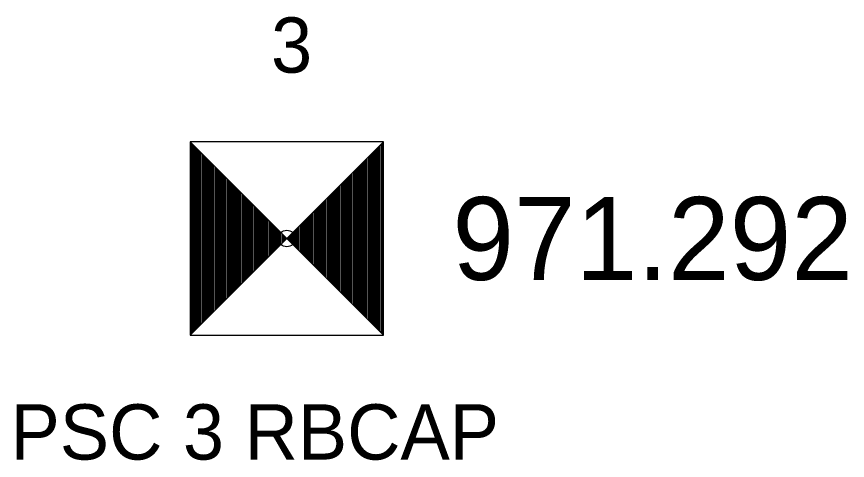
# Model space of a CAD drawing. Extents: x 1393163 to 1398407, y 1072670 to 1074651.
# Drawn here: x 1393937.48 to 1393952.52, y 1073673.99 to 1073682.02 of the extents above; entities that cross this region are included whole.
import ezdxf

# ---------------------------------------------------------------- set-up
doc = ezdxf.new("R2010")
doc.units = 0
for name, color, linetype in [('RD_HC_Survey', 7, 'Continuous'), ('RD_HC_Survey_ELEV', 7, 'Continuous'), ('RD_HC_txCode', 7, 'Continuous'), ('RD_SMD_Locator', 7, 'Continuous')]:
    doc.layers.add(name, color=color, linetype=linetype)

msp = doc.modelspace()

# ---------------------------------------------------------------- linework, layer by layer
at = {"layer": 'RD_HC_Survey'}
for p, q in [((1393940.624, 1073679.758), (1393944.124, 1073676.259)), ((1393944.124, 1073679.758), (1393940.624, 1073676.259)), ((1393940.649, 1073679.734), (1393940.649, 1073676.283)), ((1393944.1, 1073679.734), (1393944.1, 1073676.283)), ((1393940.674, 1073679.709), (1393940.674, 1073676.308)), ((1393940.699, 1073679.684), (1393940.699, 1073676.333)), ((1393940.723, 1073679.659), (1393940.723, 1073676.358)), ((1393940.748, 1073679.635), (1393940.748, 1073676.382)), ((1393940.773, 1073679.61), (1393940.773, 1073676.407)), ((1393940.798, 1073679.585), (1393940.798, 1073676.432)), ((1393943.951, 1073679.585), (1393943.951, 1073676.432)), ((1393943.976, 1073679.61), (1393943.976, 1073676.407)), ((1393944.001, 1073679.635), (1393944.001, 1073676.382)), ((1393944.025, 1073679.659), (1393944.025, 1073676.358)), ((1393944.05, 1073679.684), (1393944.05, 1073676.333)), ((1393944.075, 1073679.709), (1393944.075, 1073676.308)), ((1393940.822, 1073679.561), (1393940.822, 1073676.456)), ((1393940.847, 1073679.536), (1393940.847, 1073676.481)), ((1393940.872, 1073679.511), (1393940.872, 1073676.506)), ((1393940.897, 1073679.486), (1393940.897, 1073676.531)), ((1393940.921, 1073679.462), (1393940.921, 1073676.555)), ((1393940.946, 1073679.437), (1393940.946, 1073676.58)), ((1393943.803, 1073679.437), (1393943.803, 1073676.58)), ((1393943.827, 1073679.462), (1393943.827, 1073676.555)), ((1393943.852, 1073679.486), (1393943.852, 1073676.531)), ((1393943.877, 1073679.511), (1393943.877, 1073676.506)), ((1393943.902, 1073679.536), (1393943.902, 1073676.481)), ((1393943.926, 1073679.561), (1393943.926, 1073676.456)), ((1393940.971, 1073679.412), (1393940.971, 1073676.605)), ((1393940.996, 1073679.387), (1393940.996, 1073676.63)), ((1393941.02, 1073679.363), (1393941.02, 1073676.654)), ((1393941.045, 1073679.338), (1393941.045, 1073676.679)), ((1393941.07, 1073679.313), (1393941.07, 1073676.704)), ((1393941.095, 1073679.288), (1393941.095, 1073676.729)), ((1393943.654, 1073679.288), (1393943.654, 1073676.729)), ((1393943.679, 1073679.313), (1393943.679, 1073676.704)), ((1393943.704, 1073679.338), (1393943.704, 1073676.679)), ((1393943.728, 1073679.363), (1393943.728, 1073676.654)), ((1393943.753, 1073679.387), (1393943.753, 1073676.63)), ((1393943.778, 1073679.412), (1393943.778, 1073676.605)), ((1393941.119, 1073679.264), (1393941.119, 1073676.753)), ((1393941.144, 1073679.239), (1393941.144, 1073676.778)), ((1393941.169, 1073679.214), (1393941.169, 1073676.803)), ((1393941.194, 1073679.189), (1393941.194, 1073676.828)), ((1393941.218, 1073679.165), (1393941.218, 1073676.852)), ((1393941.243, 1073679.14), (1393941.243, 1073676.877)), ((1393943.506, 1073679.14), (1393943.506, 1073676.877)), ((1393943.53, 1073679.165), (1393943.53, 1073676.852)), ((1393943.555, 1073679.189), (1393943.555, 1073676.828)), ((1393943.58, 1073679.214), (1393943.58, 1073676.803)), ((1393943.605, 1073679.239), (1393943.605, 1073676.778)), ((1393943.629, 1073679.264), (1393943.629, 1073676.753)), ((1393941.268, 1073679.115), (1393941.268, 1073676.902)), ((1393941.293, 1073679.09), (1393941.293, 1073676.927)), ((1393941.317, 1073679.066), (1393941.317, 1073676.951)), ((1393941.342, 1073679.041), (1393941.342, 1073676.976)), ((1393941.367, 1073679.016), (1393941.367, 1073677.001)), ((1393941.392, 1073678.991), (1393941.392, 1073677.026)), ((1393943.357, 1073678.991), (1393943.357, 1073677.026)), ((1393943.382, 1073679.016), (1393943.382, 1073677.001)), ((1393943.407, 1073679.041), (1393943.407, 1073676.976)), ((1393943.431, 1073679.066), (1393943.431, 1073676.951)), ((1393943.456, 1073679.09), (1393943.456, 1073676.927)), ((1393943.481, 1073679.115), (1393943.481, 1073676.902)), ((1393941.416, 1073678.967), (1393941.416, 1073677.05)), ((1393941.441, 1073678.942), (1393941.441, 1073677.075)), ((1393941.466, 1073678.917), (1393941.466, 1073677.1)), ((1393941.491, 1073678.892), (1393941.491, 1073677.125)), ((1393941.515, 1073678.868), (1393941.515, 1073677.149)), ((1393941.54, 1073678.843), (1393941.54, 1073677.174)), ((1393943.209, 1073678.843), (1393943.209, 1073677.174)), ((1393943.233, 1073678.868), (1393943.233, 1073677.149)), ((1393943.258, 1073678.892), (1393943.258, 1073677.125)), ((1393943.283, 1073678.917), (1393943.283, 1073677.1)), ((1393943.308, 1073678.942), (1393943.308, 1073677.075)), ((1393943.332, 1073678.967), (1393943.332, 1073677.05)), ((1393941.565, 1073678.818), (1393941.565, 1073677.199)), ((1393941.59, 1073678.793), (1393941.59, 1073677.224)), ((1393941.614, 1073678.769), (1393941.614, 1073677.248)), ((1393941.639, 1073678.744), (1393941.639, 1073677.273)), ((1393941.664, 1073678.719), (1393941.664, 1073677.298)), ((1393941.689, 1073678.694), (1393941.689, 1073677.323)), ((1393943.06, 1073678.694), (1393943.06, 1073677.323)), ((1393943.085, 1073678.719), (1393943.085, 1073677.298)), ((1393943.11, 1073678.744), (1393943.11, 1073677.273)), ((1393943.134, 1073678.769), (1393943.134, 1073677.248)), ((1393943.159, 1073678.793), (1393943.159, 1073677.224)), ((1393943.184, 1073678.818), (1393943.184, 1073677.199)), ((1393941.713, 1073678.67), (1393941.713, 1073677.347)), ((1393941.738, 1073678.645), (1393941.738, 1073677.372)), ((1393941.763, 1073678.62), (1393941.763, 1073677.397)), ((1393941.788, 1073678.595), (1393941.788, 1073677.422)), ((1393941.812, 1073678.571), (1393941.812, 1073677.446)), ((1393941.837, 1073678.546), (1393941.837, 1073677.471)), ((1393941.862, 1073678.521), (1393941.862, 1073677.496)), ((1393942.887, 1073678.521), (1393942.887, 1073677.496)), ((1393942.912, 1073678.546), (1393942.912, 1073677.471)), ((1393942.936, 1073678.571), (1393942.936, 1073677.446)), ((1393942.961, 1073678.595), (1393942.961, 1073677.422)), ((1393942.986, 1073678.62), (1393942.986, 1073677.397)), ((1393943.011, 1073678.645), (1393943.011, 1073677.372)), ((1393943.035, 1073678.67), (1393943.035, 1073677.347)), ((1393941.887, 1073678.496), (1393941.887, 1073677.521)), ((1393941.911, 1073678.472), (1393941.911, 1073677.545)), ((1393941.936, 1073678.447), (1393941.936, 1073677.57)), ((1393941.961, 1073678.422), (1393941.961, 1073677.595)), ((1393941.986, 1073678.397), (1393941.986, 1073677.62)), ((1393942.01, 1073678.373), (1393942.01, 1073677.644)), ((1393942.738, 1073678.373), (1393942.738, 1073677.644)), ((1393942.763, 1073678.397), (1393942.763, 1073677.62)), ((1393942.788, 1073678.422), (1393942.788, 1073677.595)), ((1393942.813, 1073678.447), (1393942.813, 1073677.57)), ((1393942.837, 1073678.472), (1393942.837, 1073677.545)), ((1393942.862, 1073678.496), (1393942.862, 1073677.521)), ((1393942.035, 1073678.348), (1393942.035, 1073677.669)), ((1393942.06, 1073678.323), (1393942.06, 1073677.694)), ((1393942.085, 1073678.298), (1393942.085, 1073677.719)), ((1393942.109, 1073678.274), (1393942.109, 1073677.743)), ((1393942.134, 1073678.249), (1393942.134, 1073677.768)), ((1393942.159, 1073678.224), (1393942.159, 1073677.793)), ((1393942.59, 1073678.224), (1393942.59, 1073677.793)), ((1393942.615, 1073678.249), (1393942.615, 1073677.768)), ((1393942.639, 1073678.274), (1393942.639, 1073677.743)), ((1393942.664, 1073678.298), (1393942.664, 1073677.719)), ((1393942.689, 1073678.323), (1393942.689, 1073677.694)), ((1393942.714, 1073678.348), (1393942.714, 1073677.669)), ((1393942.184, 1073678.199), (1393942.184, 1073677.818)), ((1393942.208, 1073678.175), (1393942.208, 1073677.842)), ((1393942.233, 1073678.15), (1393942.233, 1073677.867)), ((1393942.258, 1073678.125), (1393942.258, 1073677.892)), ((1393942.283, 1073678.1), (1393942.283, 1073677.917)), ((1393942.307, 1073678.076), (1393942.307, 1073677.941)), ((1393942.441, 1073678.076), (1393942.441, 1073677.941)), ((1393942.466, 1073678.1), (1393942.466, 1073677.917)), ((1393942.491, 1073678.125), (1393942.491, 1073677.892)), ((1393942.516, 1073678.15), (1393942.516, 1073677.867)), ((1393942.54, 1073678.175), (1393942.54, 1073677.842)), ((1393942.565, 1073678.199), (1393942.565, 1073677.818)), ((1393942.332, 1073678.051), (1393942.332, 1073677.966)), ((1393942.357, 1073678.026), (1393942.357, 1073677.991)), ((1393942.392, 1073678.026), (1393942.392, 1073677.991)), ((1393942.417, 1073678.051), (1393942.417, 1073677.966))]:
    msp.add_line(p, q, dxfattribs=at)
msp.add_lwpolyline([(1393944.124, 1073679.758), (1393940.624, 1073679.758), (1393940.624, 1073676.259), (1393944.124, 1073676.259)], close=True, dxfattribs=at)
at = {"layer": 'RD_SMD_Locator'}
msp.add_circle((1393942.374, 1073678.009), 0.15, dxfattribs=at)

# ---------------------------------------------------------------- texts
at = {"layer": 'RD_HC_Survey_ELEV'}
msp.add_text('971.292', height=1.5, dxfattribs=at).set_placement((1393945.374, 1073677.259))
at = {"layer": 'RD_HC_txCode'}
for s, p in [('3', (1393942.091, 1073681.009)), ('PSC 3 RBCAP', (1393937.374, 1073674.009))]:
    msp.add_text(s, height=1, dxfattribs=at).set_placement(p)

doc.saveas('drawing.dxf')
